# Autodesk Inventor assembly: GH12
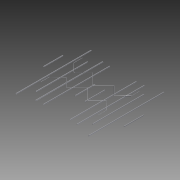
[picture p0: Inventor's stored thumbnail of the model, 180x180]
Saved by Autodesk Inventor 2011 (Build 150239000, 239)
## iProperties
Created: 2014-02
Part Number: GH12
Document SubType Name: Assembly
Designer: Evgeny
Author: Evgeny
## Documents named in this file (8)
- D:\Old Computer\Евгений\Autodesk\Projects\Antenna\GH12\GH12.iam
- D:\Old Computer\Евгений\Autodesk\Projects\Antenna\GH12\L1.ipt
- D:\Old Computer\Евгений\Autodesk\Projects\Antenna\GH12\L2.ipt
- D:\Old Computer\Евгений\Autodesk\Projects\Antenna\GH12\L3.ipt
- D:\Old Computer\Евгений\Autodesk\Projects\Antenna\GH12\L4.ipt
- D:\Old Computer\Евгений\Autodesk\Projects\Antenna\GH12\L5.ipt
- D:\Old Computer\Евгений\Autodesk\Projects\Antenna\GH12\L6.ipt
- D:\Old Computer\Евгений\Autodesk\Projects\Antenna\GH12\Ant1.ipt
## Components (14 placed, 7 different names)
1. L1:1 — Совмещение:1, Заподлицо:1, Заподлицо:2, Заподлицо:4, Совмещение:14, Заподлицо:6, Заподлицо:8
2. L1:2 — Совмещение:2, Совмещение:3, Заподлицо:1, Совмещение:4
3. L2:1 — Совмещение:6, Совмещение:7, Заподлицо:2, Заподлицо:3
4. L2:2 — Совмещение:8, Совмещение:9, Заподлицо:3
5. L3:1 — Совмещение:10, Совмещение:11, Заподлицо:4, Заподлицо:5
6. L3:2 — Совмещение:12, Совмещение:13, Заподлицо:5
7. L4:1 — Совмещение:15, Совмещение:16, Заподлицо:7
8. L4:2 — Совмещение:17, Совмещение:18, Заподлицо:6, Заподлицо:7
9. L5:1 — Совмещение:19, Совмещение:20, Заподлицо:8, Заподлицо:9
10. L5:2 — Совмещение:21, Совмещение:22, Заподлицо:9
11. L6:1 — Совмещение:23, Совмещение:24
12. L6:2 — Совмещение:25, Совмещение:26
13. Ant1:1 — Совмещение:27, Совмещение:28, Совмещение:29, Совмещение:30, Совмещение:34
14. Ant1:2 — Совмещение:31, Совмещение:32, Совмещение:33, Совмещение:34
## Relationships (42: Mate 33, Flush 9)
- Совмещение:1 [Mate]: L1:1
- Совмещение:2 [Mate]: L1:2
- Совмещение:3 [Mate]: L1:2
- Заподлицо:1 [Flush]: L1:1 ↔ L1:2
- Совмещение:4 [Mate]: L1:2
- Совмещение:6 [Mate]: L2:1
- Совмещение:7 [Mate]: L2:1
- Совмещение:8 [Mate]: L2:2
- Совмещение:9 [Mate]: L2:2
- Заподлицо:2 [Flush]: L1:1 ↔ L2:1
- Заподлицо:3 [Flush]: L2:1 ↔ L2:2
- Совмещение:10 [Mate]: L3:1
- Совмещение:11 [Mate]: L3:1
- Заподлицо:4 [Flush]: L1:1 ↔ L3:1
- Совмещение:12 [Mate]: L3:2
- Совмещение:13 [Mate]: L3:2
- Заподлицо:5 [Flush]: L3:1 ↔ L3:2
- Совмещение:14 [Mate]: L1:1
- Совмещение:15 [Mate]: L4:1
- Совмещение:16 [Mate]: L4:1
- Совмещение:17 [Mate]: L4:2
- Совмещение:18 [Mate]: L4:2
- Заподлицо:6 [Flush]: L1:1 ↔ L4:2
- Заподлицо:7 [Flush]: L4:1 ↔ L4:2
- Совмещение:19 [Mate]: L5:1
- Совмещение:20 [Mate]: L5:1
- Совмещение:21 [Mate]: L5:2
- Совмещение:22 [Mate]: L5:2
- Заподлицо:8 [Flush]: L1:1 ↔ L5:1
- Заподлицо:9 [Flush]: L5:1 ↔ L5:2
- Совмещение:23 [Mate]: L6:1
- Совмещение:24 [Mate]: L6:1
- Совмещение:25 [Mate]: L6:2
- Совмещение:26 [Mate]: L6:2
- Совмещение:27 [Mate]: Ant1:1
- Совмещение:28 [Mate]: Ant1:1
- Совмещение:29 [Mate]: Ant1:1
- Совмещение:30 [Mate]: Ant1:1
- Совмещение:31 [Mate]: Ant1:2
- Совмещение:32 [Mate]: Ant1:2
- Совмещение:33 [Mate]: Ant1:2
- Совмещение:34 [Mate]: Ant1:1 ↔ Ant1:2
